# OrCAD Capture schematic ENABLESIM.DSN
size C; rev: A
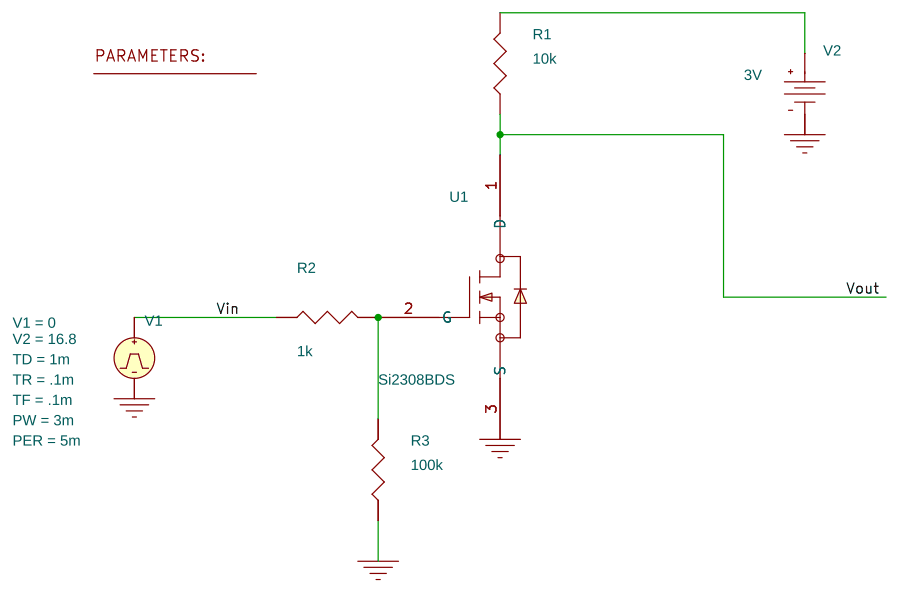
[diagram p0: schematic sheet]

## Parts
1  PARAM
R1  10k
R2  1k
R3  100k
U1  Si2308BDS
V1  VPULSE
V2  VDC

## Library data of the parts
1 = PARAM: RVAL: 150
R1-R3 = R
U1 = Si2308BDS
V1 = VPULSE: PER: 5m; PW: 3m; TD: 1m; TF: .1m; TR: .1m; V1: 0; V2: 16.8
V2 = VDC: DC: 3V

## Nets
Vin: R2.1 V1.1(+)
0: R3.1 U1.3(S) V1.2(-) V2.1(-)
Vout: R1.1 U1.1(D)
N00193: R1.2 V2.0(+)
N00719: R2.2 R3.2 U1.2(G)
